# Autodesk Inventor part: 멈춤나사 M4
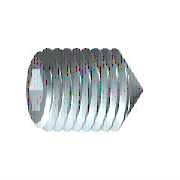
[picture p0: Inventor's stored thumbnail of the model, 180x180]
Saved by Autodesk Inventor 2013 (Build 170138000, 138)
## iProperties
Created: 2012-02
Part Number: 멈춤나사 M4
Material: 강철, 연강
Description: 6각 소켓 머리 없는 멈춤 나사
Document SubType Name: Modeling
Standard: KS B 1028
Designer: mduedu
Standards Organization: KS
Language: ko-KR
Size Designation: 원추점 M4x10
Categories: <MemberInstance><Categories><Category DisplayName="조임쇠" InternalName="e4da775c-781d-43d5-af7c-5136215cf5a6" Mnemonic="FSTN"><Category DisplayName="볼트" InternalN
Density: 7.86 g/cm^3
Mass: 0.792069 g
Surface Area: 1.48192 cm^2
Volume: 0.100772 cm^3
Author: mduedu
IsCustomPart: 1
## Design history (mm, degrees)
sketch "스케치1"
  geometry: L1 (0, 0)-(6.833, 0); L2 (10, 1.155)-(10, 2); L3 (10, 2)-(0, 2); L4 (10, 1.155)-(7.5, 1.155); L5 (7.5, 1.155)-(6.833, 0); L6 (0, -0.4)-(0, 2.4) reference; L7 (0, 2)-(0, 0)
  constraints: 13 end point, 3 parallel, 1 collinear, 1 perpendicular, 1 point on line
  dimensions: "d0" = 2.5 distance of L2.start L4.end (= INTI); "d1" = 60 deg angle of L5 L1; "d2" = 4 diameter of L3 L1 (= NND); "d3" = 2.3094 diameter of L4 L1 (= 1.1547 x SW); "d5" = 10 distance from line of L2 L3.end (= NLG)
revolve "본체" sketch "스케치1" stored, may be unused: angle "d6" = 90 deg
sketch "스케치2"
  geometry: L1 (-0.577, 1)-(0.577, 1); L2 (0.577, 1)-(1.155, 0); L3 (1.155, 0)-(0.577, -1); L4 (0.577, -1)-(-0.577, -1); L5 (-0.577, -1)-(-1.155, 0); L6 (-1.155, 0)-(-0.577, 1); 3 further points
  constraints: 12 end point, 1 coincident, 1 horizontal, 13 other
extrude "슬롯" join sketch "스케치2" taper "d7" = 0 deg; stored distance "d21" = 10
workaxis "Work Axis1"
workplane "Work Plane1"
sketch "스케치4"
  geometry: L1 (-5, 0.2)-(-3.2, 2) reference; L2 (-5, -0.2)-(-3.2, -2) reference; L3 (-3.2, 2)-(-5.2, 0); L4 (-3.2, -2)-(-5.2, 0); 2 further points
  constraints: 4 end point, 2 collinear, 1 coincident
body "Solid1"
feature "스레드" dims "d12" = 10 (= NLG), "d13" = 0
chamfer "모따기1" distance "d8" = 1.8 (computed from NND, SPD, FAWI); stored, may be unused: angle "d9" = 45 deg (= FAWI), second distance "d34" = 1.8 (computed from NND, SPD, FAWI)
chamfer "모따기2" distance "d10" = 0.42941 (= -0.5 x GD1 + 0.5 x NND); stored, may be unused: angle "d11" = 45 deg (= FAWI), second distance "d35" = 0.42941 (= -0.5 x GD1 + 0.5 x NND)
other parameters: "NND" = 4 [user parameter; used in 5 equation terms], "NLG" = 10 [user parameter; used in 2 equation terms], "INTI" = 2.5 [user parameter; used in 1 equation term], "FAWI" = 45 deg [user parameter; used in 4 equation terms], "SW" = 2 [user parameter; used in 2 equation terms], "GD1" = 3.14117 (= THREADDIA - 1.2269 x PTC) [user parameter; used in 2 equation terms], "d4" = 0, "FAWI1" = 45 deg [user parameter], "SPD" = 0.4 [user parameter; used in 2 equation terms], "d36" = 0, "d37" = 0, "GUL" = 0.42941 (= 0.61345 x PTC) [user parameter], "TPU" = 14.28571 (computed from PTC) [user parameter], "TOA" = 30 deg [user parameter], "THREADDIA" = 4 [user parameter; used in 1 equation term], "PTC" = 0.7 [user parameter; used in 4 equation terms], "GAL" = 0.42941 (= 0.61345 x PTC) [user parameter], "E0" = 2.31 (= 1.155 x SW) [user parameter]
